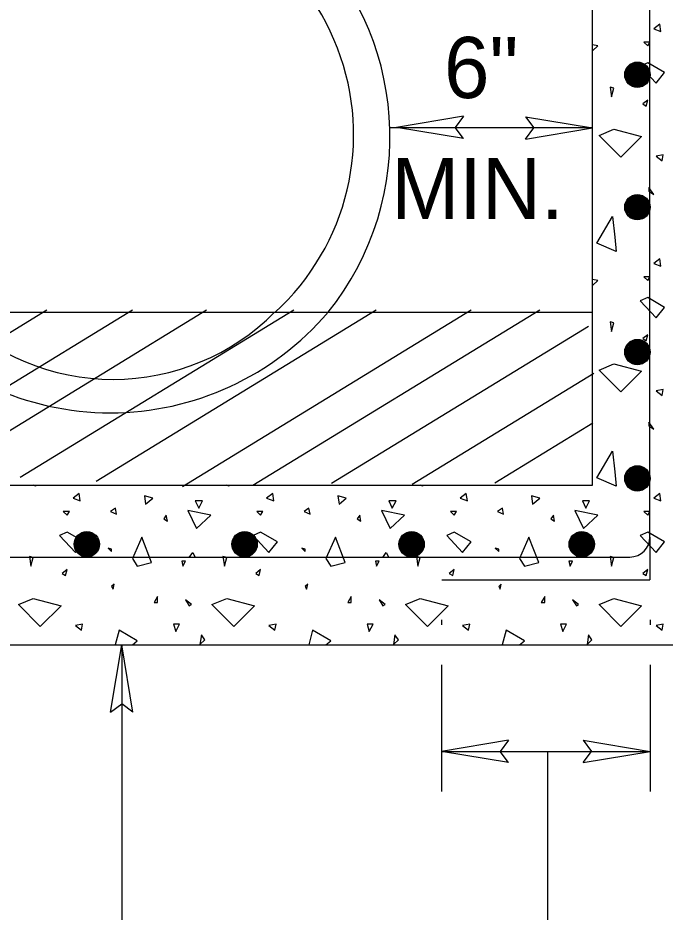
# Model space of a CAD drawing. Extents: x 5.8 to 18, y -5.2 to 5.4.
# Drawn here: x 7.37 to 8.006, y -2.394 to -1.516 of the extents above; entities that cross this region are included whole.
import ezdxf

# ---------------------------------------------------------------- set-up
doc = ezdxf.new("R2010")
doc.units = 0
for name, color, linetype in [('DETL-DIMS', 7, 'Continuous'), ('DETL-LINE', 7, 'Continuous'), ('DETL-NOTE', 7, 'Continuous'), ('DETL-PATT', 7, 'Continuous')]:
    doc.layers.add(name, color=color, linetype=linetype)

msp = doc.modelspace()

# ---------------------------------------------------------------- linework, layer by layer
at = {"layer": 'DETL-DIMS'}
for p, q in [((7.80765, -1.61271), (7.74176, -1.62369)), ((7.80765, -1.61271), (7.79941, -1.62369)), ((7.86847, -1.61322), (7.93435, -1.6242)), ((7.86847, -1.61322), (7.87671, -1.6242)), ((7.93435, -1.6242), (7.73541, -1.6242)), ((7.80765, -1.63467), (7.74176, -1.62369)), ((7.80765, -1.63467), (7.79941, -1.62369)), ((7.86847, -1.63518), (7.93435, -1.6242)), ((7.86847, -1.63518), (7.87671, -1.6242)), ((7.786, -2.10702), (7.786, -2.11216)), ((7.99098, -2.10702), (7.99098, -2.11216)), ((7.46114, -2.19765), (7.47212, -2.13177)), ((7.4831, -2.19765), (7.47212, -2.13177)), ((7.47212, -2.13177), (7.47212, -2.45765)), ((7.786, -2.15138), (7.786, -2.27557)), ((7.99098, -2.15138), (7.99098, -2.27557)), ((7.46114, -2.19765), (7.47212, -2.18942)), ((7.4831, -2.19765), (7.47212, -2.18942)), ((7.85188, -2.22538), (7.786, -2.23636)), ((7.85188, -2.22538), (7.786, -2.23636)), ((7.85188, -2.22538), (7.84365, -2.23636)), ((7.85188, -2.22538), (7.84365, -2.23636)), ((7.9251, -2.22538), (7.99098, -2.23636)), ((7.9251, -2.22538), (7.93333, -2.23636)), ((7.786, -2.23636), (7.99098, -2.23636)), ((7.85188, -2.24734), (7.786, -2.23636)), ((7.85188, -2.24734), (7.786, -2.23636)), ((7.85188, -2.24734), (7.84365, -2.23636)), ((7.85188, -2.24734), (7.84365, -2.23636)), ((7.89024, -2.23636), (7.89024, -2.87251)), ((7.9251, -2.24734), (7.99098, -2.23636)), ((7.9251, -2.24734), (7.93333, -2.23636))]:
    msp.add_line(p, q, dxfattribs=at)
at = {"layer": 'DETL-LINE'}
for p, q in [((7.93435, -1.97495), (7.93435, -0.73934)), ((7.99071, -2.02593), (7.99071, -1.28177)), ((7.00843, -1.80506), (7.93435, -1.80506)), ((7.00843, -1.97495), (7.93435, -1.97495)), ((7.99071, -2.02593), (7.99071, -2.06781)), ((6.94996, -2.04542), (7.9711, -2.04542)), ((7.78643, -2.06781), (7.99071, -2.06781)), ((6.87914, -2.13177), (8.0651, -2.13177))]:
    msp.add_line(p, q, dxfattribs=at)
for points in [[(7.98965, -1.91291), (7.98965, -1.91659), (7.99447, -1.91997)], [(7.84482, -2.07216), (7.84227, -2.07444), (7.84369, -2.07698)]]:
    msp.add_lwpolyline(points, close=True, dxfattribs=at)
for centre, radius in [((7.97844, -1.57189), 0.01247), ((7.97833, -1.57179), 0.01163), ((7.97722, -1.57179), 0.01009), ((7.97847, -1.57208), 0.01122), ((7.9788, -1.57261), 0.011), ((7.97875, -1.57222), 0.01024), ((7.97902, -1.57228), 0.00969), ((7.97763, -1.5713), 0.00834), ((7.9791, -1.57255), 0.00918), ((7.97743, -1.57228), 0.00724), ((7.97924, -1.57269), 0.00876), ((7.9791, -1.57291), 0.00835), ((7.9768, -1.57269), 0.00578), ((7.97931, -1.57291), 0.00814), ((7.97916, -1.57277), 0.00786), ((7.97951, -1.57297), 0.00751), ((7.97959, -1.57283), 0.00704), ((7.97776, -1.57242), 0.00467), ((7.97965, -1.57275), 0.00655), ((7.97965, -1.57261), 0.006), ((7.97973, -1.57277), 0.00565), ((7.97973, -1.57283), 0.0051), ((7.97994, -1.57326), 0.00488), ((7.98006, -1.57332), 0.00445), ((7.98006, -1.5732), 0.0039), ((7.98022, -1.5731), 0.00377), ((7.98022, -1.57346), 0.00347), ((7.98035, -1.57318), 0.00333), ((7.98041, -1.57326), 0.00285), ((7.98022, -1.57304), 0.00238), ((7.98049, -1.57334), 0.00212), ((7.98057, -1.57332), 0.00175), ((7.98071, -1.5734), 0.00133), ((7.98071, -1.57326), 0.00118), ((7.98112, -1.57332), 0.00148), ((7.98069, -1.57326), 0.000769), ((7.98055, -1.57326), 0.000362), ((7.98084, -1.57326), 0.00023), ((7.97844, -1.70197), 0.01247), ((7.97833, -1.70187), 0.01163), ((7.97722, -1.70187), 0.01009), ((7.97847, -1.70216), 0.01122), ((7.9788, -1.70269), 0.011), ((7.97875, -1.7023), 0.01024), ((7.97763, -1.70138), 0.00834), ((7.97902, -1.70236), 0.00969), ((7.9791, -1.70263), 0.00918), ((7.97924, -1.70277), 0.00876), ((7.97743, -1.70236), 0.00724), ((7.9791, -1.70298), 0.00835), ((7.9768, -1.70277), 0.00578), ((7.97931, -1.70298), 0.00814), ((7.97916, -1.70285), 0.00786), ((7.97951, -1.70304), 0.00751), ((7.97959, -1.70291), 0.00704), ((7.97776, -1.70249), 0.00467), ((7.97965, -1.70283), 0.00655), ((7.97965, -1.70269), 0.006), ((7.97973, -1.70285), 0.00565), ((7.97973, -1.70291), 0.0051), ((7.97994, -1.70334), 0.00488), ((7.98006, -1.7034), 0.00445), ((7.98006, -1.70328), 0.0039), ((7.98022, -1.70318), 0.00377), ((7.98022, -1.70353), 0.00347), ((7.98035, -1.70326), 0.00333), ((7.98041, -1.70334), 0.00285), ((7.98022, -1.70312), 0.00238), ((7.98049, -1.70342), 0.00212), ((7.98057, -1.7034), 0.00175), ((7.98071, -1.70348), 0.00133), ((7.98071, -1.70334), 0.00118), ((7.98112, -1.7034), 0.00148), ((7.98069, -1.70334), 0.000769), ((7.98055, -1.70334), 0.000362), ((7.98084, -1.70334), 0.00023), ((7.97844, -1.84421), 0.01247), ((7.97833, -1.8441), 0.01163), ((7.97722, -1.8441), 0.01009), ((7.97847, -1.8444), 0.01122), ((7.9788, -1.84493), 0.011), ((7.97875, -1.84453), 0.01024), ((7.97902, -1.84459), 0.00969), ((7.97763, -1.84361), 0.00834), ((7.9791, -1.84487), 0.00918), ((7.97743, -1.84459), 0.00724), ((7.97924, -1.845), 0.00876), ((7.9791, -1.84522), 0.00835), ((7.9768, -1.845), 0.00578), ((7.97931, -1.84522), 0.00814), ((7.97916, -1.84508), 0.00786), ((7.97951, -1.84528), 0.00751), ((7.97959, -1.84514), 0.00704), ((7.97776, -1.84473), 0.00467), ((7.97965, -1.84506), 0.00655), ((7.97965, -1.84493), 0.006), ((7.97973, -1.84508), 0.00565), ((7.97973, -1.84514), 0.0051), ((7.97994, -1.84557), 0.00488), ((7.98006, -1.84563), 0.00445), ((7.98006, -1.84551), 0.0039), ((7.98022, -1.84542), 0.00377), ((7.98022, -1.84577), 0.00347), ((7.98035, -1.84549), 0.00333), ((7.98041, -1.84557), 0.00285), ((7.98022, -1.84536), 0.00238), ((7.98049, -1.84565), 0.00212), ((7.98057, -1.84563), 0.00175), ((7.98071, -1.84571), 0.00133), ((7.98071, -1.84557), 0.00118), ((7.98112, -1.84563), 0.00148), ((7.98069, -1.84557), 0.000769), ((7.98055, -1.84557), 0.000362), ((7.98084, -1.84557), 0.00023), ((7.97844, -1.96825), 0.01247), ((7.97833, -1.96814), 0.01163), ((7.97847, -1.96844), 0.01122), ((7.97722, -1.96814), 0.01009), ((7.9788, -1.96897), 0.011), ((7.97875, -1.96857), 0.01024), ((7.97763, -1.96765), 0.00834), ((7.97902, -1.96863), 0.00969), ((7.9791, -1.96891), 0.00918), ((7.97743, -1.96863), 0.00724), ((7.97924, -1.96904), 0.00876), ((7.9791, -1.96926), 0.00835), ((7.9768, -1.96904), 0.00578), ((7.97931, -1.96926), 0.00814), ((7.97916, -1.96912), 0.00786), ((7.97951, -1.96932), 0.00751), ((7.97959, -1.96918), 0.00704), ((7.97776, -1.96877), 0.00467), ((7.97965, -1.9691), 0.00655), ((7.97965, -1.96897), 0.006), ((7.97973, -1.96912), 0.00565), ((7.97973, -1.96918), 0.0051), ((7.97994, -1.96961), 0.00488), ((7.98006, -1.96967), 0.00445), ((7.98006, -1.96955), 0.0039), ((7.98022, -1.96946), 0.00377), ((7.98022, -1.96981), 0.00347), ((7.98035, -1.96953), 0.00333), ((7.98041, -1.96961), 0.00285), ((7.98022, -1.9694), 0.00238), ((7.98049, -1.96969), 0.00212), ((7.98057, -1.96967), 0.00175), ((7.98071, -1.96975), 0.00133), ((7.98071, -1.96961), 0.00118), ((7.98112, -1.96967), 0.00148), ((7.98069, -1.96961), 0.000769), ((7.98055, -1.96961), 0.000362), ((7.98084, -1.96961), 0.00023), ((7.43788, -2.03295), 0.01247), ((7.43778, -2.03285), 0.01163), ((7.43666, -2.03285), 0.01009), ((7.43791, -2.03314), 0.01122), ((7.43825, -2.03367), 0.011), ((7.43819, -2.03328), 0.01024), ((7.43707, -2.03236), 0.00834), ((7.43846, -2.03334), 0.00969), ((7.43854, -2.03361), 0.00918), ((7.43687, -2.03334), 0.00724), ((7.43868, -2.03375), 0.00876), ((7.43854, -2.03396), 0.00835), ((7.43625, -2.03375), 0.00578), ((7.43876, -2.03396), 0.00814), ((7.4386, -2.03383), 0.00786), ((7.43895, -2.03402), 0.00751), ((7.43903, -2.03389), 0.00704), ((7.43909, -2.03381), 0.00655), ((7.43909, -2.03367), 0.006), ((7.59278, -2.03295), 0.01247), ((7.59268, -2.03285), 0.01163), ((7.59156, -2.03285), 0.01009), ((7.59281, -2.03314), 0.01122), ((7.59315, -2.03367), 0.011), ((7.59309, -2.03328), 0.01024), ((7.59197, -2.03236), 0.00834), ((7.59336, -2.03334), 0.00969), ((7.59344, -2.03361), 0.00918), ((7.59178, -2.03334), 0.00724), ((7.59358, -2.03375), 0.00876), ((7.59344, -2.03396), 0.00835), ((7.59115, -2.03375), 0.00578), ((7.59366, -2.03396), 0.00814), ((7.5935, -2.03383), 0.00786), ((7.59385, -2.03402), 0.00751), ((7.59393, -2.03389), 0.00704), ((7.59399, -2.03381), 0.00655), ((7.59399, -2.03367), 0.006), ((7.75675, -2.03295), 0.01247), ((7.75664, -2.03285), 0.01163), ((7.75552, -2.03285), 0.01009), ((7.75678, -2.03314), 0.01122), ((7.75711, -2.03367), 0.011), ((7.75705, -2.03328), 0.01024), ((7.75593, -2.03236), 0.00834), ((7.75732, -2.03334), 0.00969), ((7.7574, -2.03361), 0.00918), ((7.75574, -2.03334), 0.00724), ((7.75754, -2.03375), 0.00876), ((7.7574, -2.03396), 0.00835), ((7.75511, -2.03375), 0.00578), ((7.75762, -2.03396), 0.00814), ((7.75746, -2.03383), 0.00786), ((7.75781, -2.03402), 0.00751), ((7.75789, -2.03389), 0.00704), ((7.75795, -2.03381), 0.00655), ((7.75795, -2.03367), 0.006), ((7.9238, -2.03295), 0.01247), ((7.9237, -2.03285), 0.01163), ((7.92258, -2.03285), 0.01009), ((7.92383, -2.03314), 0.01122), ((7.92417, -2.03367), 0.011), ((7.92411, -2.03328), 0.01024), ((7.92299, -2.03236), 0.00834), ((7.92438, -2.03334), 0.00969), ((7.92446, -2.03361), 0.00918), ((7.9228, -2.03334), 0.00724), ((7.9246, -2.03375), 0.00876), ((7.92446, -2.03396), 0.00835), ((7.92217, -2.03375), 0.00578), ((7.92468, -2.03396), 0.00814), ((7.92452, -2.03383), 0.00786), ((7.92487, -2.03402), 0.00751), ((7.92495, -2.03389), 0.00704), ((7.92501, -2.03381), 0.00655), ((7.92501, -2.03367), 0.006), ((7.43721, -2.03347), 0.00467), ((7.43917, -2.03383), 0.00565), ((7.43917, -2.03389), 0.0051), ((7.43938, -2.03432), 0.00488), ((7.4395, -2.03438), 0.00445), ((7.4395, -2.03426), 0.0039), ((7.43966, -2.03416), 0.00377), ((7.43966, -2.03451), 0.00347), ((7.4398, -2.03424), 0.00333), ((7.43985, -2.03432), 0.00285), ((7.43966, -2.0341), 0.00238), ((7.43993, -2.03439), 0.00212), ((7.44001, -2.03438), 0.00175), ((7.44015, -2.03445), 0.00133), ((7.44015, -2.03432), 0.00118), ((7.44056, -2.03438), 0.00148), ((7.44013, -2.03432), 0.000769), ((7.43999, -2.03432), 0.000362), ((7.44029, -2.03432), 0.00023), ((7.59211, -2.03347), 0.00467), ((7.59407, -2.03383), 0.00565), ((7.59407, -2.03389), 0.0051), ((7.59429, -2.03432), 0.00488), ((7.5944, -2.03438), 0.00445), ((7.5944, -2.03426), 0.0039), ((7.59456, -2.03416), 0.00377), ((7.59456, -2.03451), 0.00347), ((7.5947, -2.03424), 0.00333), ((7.59476, -2.03432), 0.00285), ((7.59456, -2.0341), 0.00238), ((7.59483, -2.03439), 0.00212), ((7.59491, -2.03438), 0.00175), ((7.59505, -2.03445), 0.00133), ((7.59505, -2.03432), 0.00118), ((7.59546, -2.03438), 0.00148), ((7.59503, -2.03432), 0.000769), ((7.59489, -2.03432), 0.000362), ((7.59519, -2.03432), 0.00023), ((7.75607, -2.03347), 0.00467), ((7.75803, -2.03383), 0.00565), ((7.75803, -2.03389), 0.0051), ((7.75825, -2.03432), 0.00488), ((7.75836, -2.03438), 0.00445), ((7.75836, -2.03426), 0.0039), ((7.75852, -2.03416), 0.00377), ((7.75852, -2.03451), 0.00347), ((7.75866, -2.03424), 0.00333), ((7.75872, -2.03432), 0.00285), ((7.75852, -2.0341), 0.00238), ((7.7588, -2.03439), 0.00212), ((7.75887, -2.03438), 0.00175), ((7.75901, -2.03445), 0.00133), ((7.75901, -2.03432), 0.00118), ((7.75942, -2.03438), 0.00148), ((7.75899, -2.03432), 0.000769), ((7.75885, -2.03432), 0.000362), ((7.75915, -2.03432), 0.00023), ((7.92313, -2.03347), 0.00467), ((7.92509, -2.03383), 0.00565), ((7.92509, -2.03389), 0.0051), ((7.92531, -2.03432), 0.00488), ((7.92542, -2.03438), 0.00445), ((7.92542, -2.03426), 0.0039), ((7.92558, -2.03416), 0.00377), ((7.92558, -2.03451), 0.00347), ((7.92572, -2.03424), 0.00333), ((7.92578, -2.03432), 0.00285), ((7.92558, -2.0341), 0.00238), ((7.92585, -2.03439), 0.00212), ((7.92593, -2.03438), 0.00175), ((7.92607, -2.03445), 0.00133), ((7.92607, -2.03432), 0.00118), ((7.92648, -2.03438), 0.00148), ((7.92605, -2.03432), 0.000769), ((7.92591, -2.03432), 0.000362), ((7.92621, -2.03432), 0.00023)]:
    msp.add_circle(centre, radius, dxfattribs=at)
for centre, radius, start, end in [((7.461, -1.63265), 0.27454, 321.09641, 218.89267), ((7.46386, -1.6306), 0.23592, 312.23829, 227.67559), ((7.46096, -1.62322), 0.28059, 220.39706, 319.60294), ((7.46362, -1.64743), 0.22364, 224.81552, 315.18448), ((7.9711, -2.02581), 0.01961, 270, 360)]:
    msp.add_arc(centre, radius, start, end, dxfattribs=at)
at = {"layer": 'DETL-PATT'}
for p, q in [((7.12051, -1.97287), (7.39867, -1.80287)), ((7.20835, -1.97051), (7.48267, -1.80287)), ((7.28114, -1.97044), (7.55529, -1.80287)), ((7.37227, -1.96718), (7.64114, -1.80287)), ((7.44694, -1.97087), (7.7218, -1.80287)), ((7.53188, -1.97604), (7.81522, -1.80287)), ((7.60094, -1.97502), (7.88263, -1.80287)), ((7.67796, -1.97306), (7.93047, -1.81875)), ((7.75733, -1.974), (7.93569, -1.86498)), ((7.83859, -1.97255), (7.93471, -1.91381))]:
    msp.add_line(p, q, dxfattribs=at)
for points in [[(8.00039, -1.52216), (7.99447, -1.52695), (8.00153, -1.52949)], [(7.98486, -1.53993), (7.98851, -1.54361), (7.99078, -1.53993)], [(7.98118, -1.56365), (7.99671, -1.58032), (8.00518, -1.56985), (7.98851, -1.56028)], [(7.95153, -1.58397), (7.95294, -1.59357), (7.95522, -1.5851)], [(7.98373, -1.60063), (7.9871, -1.60291), (7.98851, -1.59698)], [(7.95522, -1.62549), (7.98259, -1.63255), (7.96227, -1.65287), (7.94082, -1.63142)], [(7.99671, -1.65173), (8.00263, -1.65655), (8.00376, -1.65063)], [(7.98965, -1.68251), (7.98965, -1.6862), (7.99447, -1.68957)], [(7.95635, -1.73138), (7.95745, -1.74549), (7.93855, -1.7373), (7.95408, -1.71102)], [(8.00039, -1.75255), (7.99447, -1.75734), (8.00153, -1.75989)], [(7.98486, -1.77032), (7.98851, -1.774), (7.99078, -1.77032)], [(7.98118, -1.79404), (7.99671, -1.81071), (8.00518, -1.80028), (7.98851, -1.79067)], [(7.95153, -1.8144), (7.95294, -1.82397), (7.95522, -1.81549)], [(7.98373, -1.83102), (7.9871, -1.8333), (7.98851, -1.82738)], [(7.95522, -1.85589), (7.98259, -1.86295), (7.96227, -1.88326), (7.94082, -1.86181)], [(7.99671, -1.88216), (8.00263, -1.88695), (8.00376, -1.88102)], [(7.95635, -1.96177), (7.95745, -1.97589), (7.93855, -1.96769), (7.95408, -1.94146)], [(7.43031, -1.98295), (7.42439, -1.98773), (7.43145, -1.99028)], [(7.62035, -1.98295), (7.61439, -1.98773), (7.62145, -1.99028)], [(7.81035, -1.98295), (7.80443, -1.98773), (7.81149, -1.99028)], [(8.00039, -1.98295), (7.99447, -1.98773), (8.00153, -1.99028)], [(7.49439, -1.98549), (7.49553, -1.99369), (7.50259, -1.98773)], [(7.54439, -1.99028), (7.54776, -1.99734), (7.55145, -1.99028)], [(7.68443, -1.98549), (7.68557, -1.99369), (7.69263, -1.98773)], [(7.73439, -1.99028), (7.7378, -1.99734), (7.74145, -1.99028)], [(7.87447, -1.98549), (7.87557, -1.99369), (7.88263, -1.98773)], [(7.92443, -1.99028), (7.9278, -1.99734), (7.93149, -1.99028)], [(7.41478, -2.00075), (7.41847, -2.0044), (7.42071, -2.00075)], [(7.4611, -2.00075), (7.46702, -2.00326), (7.46588, -1.99734)], [(7.53706, -1.99961), (7.54553, -2.01738), (7.55965, -2.0044)], [(7.60482, -2.00075), (7.60847, -2.0044), (7.61075, -2.00075)], [(7.6511, -2.00075), (7.65706, -2.00326), (7.65592, -1.99734)], [(7.72706, -1.99961), (7.73553, -2.01738), (7.74965, -2.0044)], [(7.79482, -2.00075), (7.79851, -2.0044), (7.80075, -2.00075)], [(7.84114, -2.00075), (7.84706, -2.00326), (7.84592, -1.99734)], [(7.9171, -1.99961), (7.92557, -2.01738), (7.93969, -2.0044)], [(7.98486, -2.00075), (7.98851, -2.0044), (7.99078, -2.00075)], [(7.51333, -2.00808), (7.51698, -2.01032), (7.51588, -2.0044)], [(7.70333, -2.00808), (7.70702, -2.01032), (7.70588, -2.0044)], [(7.89337, -2.00808), (7.89706, -2.01032), (7.89592, -2.0044)], [(7.4111, -2.02444), (7.42663, -2.0411), (7.4351, -2.03067), (7.41847, -2.02106)], [(7.48733, -2.0544), (7.50145, -2.05071), (7.49188, -2.02585), (7.48255, -2.04702)], [(7.60114, -2.02444), (7.61667, -2.0411), (7.62514, -2.03067), (7.60847, -2.02106)], [(7.67737, -2.0544), (7.69149, -2.05071), (7.68188, -2.02585), (7.67259, -2.04702)], [(7.79118, -2.02444), (7.80671, -2.0411), (7.81518, -2.03067), (7.79851, -2.02106)], [(7.86741, -2.0544), (7.88153, -2.05071), (7.87192, -2.02585), (7.86259, -2.04702)], [(7.98118, -2.02444), (7.99671, -2.0411), (8.00518, -2.03067), (7.98851, -2.02106)], [(7.46224, -2.03773), (7.45882, -2.03659), (7.46224, -2.03997)], [(7.65224, -2.03773), (7.64886, -2.03659), (7.65224, -2.03997)], [(7.84227, -2.03773), (7.83886, -2.03659), (7.84227, -2.03997)], [(7.38145, -2.04479), (7.38286, -2.0544), (7.38514, -2.04593)], [(7.54184, -2.0411), (7.54439, -2.04593), (7.53847, -2.04593)], [(7.57149, -2.04479), (7.5729, -2.0544), (7.57518, -2.04593)], [(7.73188, -2.0411), (7.73439, -2.04593), (7.72847, -2.04593)], [(7.76153, -2.04479), (7.76294, -2.0544), (7.76518, -2.04593)], [(7.92188, -2.0411), (7.92443, -2.04593), (7.91851, -2.04593)], [(7.95153, -2.04479), (7.95294, -2.0544), (7.95522, -2.04593)], [(7.5311, -2.04957), (7.53224, -2.0544), (7.53478, -2.04957)], [(7.72114, -2.04957), (7.72227, -2.0544), (7.72482, -2.04957)], [(7.91118, -2.04957), (7.91227, -2.0544), (7.91482, -2.04957)], [(7.41365, -2.06146), (7.41706, -2.06369), (7.41847, -2.05777)], [(7.60369, -2.06146), (7.60706, -2.06369), (7.60847, -2.05777)], [(7.79369, -2.06146), (7.7971, -2.06369), (7.79851, -2.05777)], [(7.98373, -2.06146), (7.9871, -2.06369), (7.98851, -2.05777)], [(7.46475, -2.07216), (7.46224, -2.07444), (7.46365, -2.07698)], [(7.65478, -2.07216), (7.65224, -2.07444), (7.65365, -2.07698)], [(7.38514, -2.08628), (7.41251, -2.09334), (7.3922, -2.11369), (7.37075, -2.0922)], [(7.50741, -2.08404), (7.504, -2.08997), (7.50741, -2.08997)], [(7.53847, -2.09334), (7.54071, -2.0922), (7.53478, -2.08742)], [(7.57518, -2.08628), (7.60255, -2.09334), (7.58224, -2.11369), (7.56075, -2.0922)], [(7.69741, -2.08404), (7.69404, -2.08997), (7.69741, -2.08997)], [(7.72847, -2.09334), (7.73075, -2.0922), (7.72482, -2.08742)], [(7.76518, -2.08628), (7.79259, -2.09334), (7.77224, -2.11369), (7.75078, -2.0922)], [(7.88745, -2.08404), (7.88404, -2.08997), (7.88745, -2.08997)], [(7.91851, -2.09334), (7.92075, -2.0922), (7.91482, -2.08742)], [(7.95522, -2.08628), (7.98259, -2.09334), (7.96227, -2.11369), (7.94082, -2.0922)], [(7.42663, -2.11255), (7.43259, -2.11734), (7.43369, -2.11142)], [(7.52294, -2.11142), (7.52518, -2.11848), (7.52886, -2.11142)], [(7.61667, -2.11255), (7.62259, -2.11734), (7.62373, -2.11142)], [(7.71294, -2.11142), (7.71522, -2.11848), (7.71886, -2.11142)], [(7.80671, -2.11255), (7.81263, -2.11734), (7.81376, -2.11142)], [(7.90298, -2.11142), (7.90522, -2.11848), (7.9089, -2.11142)], [(7.99671, -2.11255), (8.00263, -2.11734), (8.00376, -2.11142)], [(7.55031, -2.12185), (7.5489, -2.13146), (7.55369, -2.12667)], [(7.74035, -2.12185), (7.73894, -2.13146), (7.74373, -2.12667)], [(7.93035, -2.12185), (7.92894, -2.13146), (7.93376, -2.12667)]]:
    msp.add_lwpolyline(points, close=True, dxfattribs=at)
for points in [[(7.93435, -1.54851), (7.93969, -1.54361), (7.93435, -1.54248)], [(7.93435, -1.77891), (7.93969, -1.774), (7.93435, -1.77287)], [(7.38733, -1.97495), (7.38741, -1.97589), (7.38525, -1.97495)], [(7.57733, -1.97495), (7.57741, -1.97589), (7.57525, -1.97495)], [(7.76737, -1.97495), (7.76745, -1.97589), (7.76529, -1.97495)], [(7.48263, -2.13177), (7.48733, -2.12781), (7.46957, -2.11734), (7.46576, -2.13177)], [(7.67267, -2.13177), (7.67737, -2.12781), (7.65957, -2.11734), (7.6558, -2.13177)], [(7.86267, -2.13177), (7.86741, -2.12781), (7.84961, -2.11734), (7.8458, -2.13177)]]:
    msp.add_lwpolyline(points, dxfattribs=at)

# ---------------------------------------------------------------- texts
at = {"layer": 'DETL-NOTE'}
for s, p in [('6"', (7.78855, -1.59479)), ('MIN.', (7.73663, -1.71361))]:
    msp.add_text(s, height=0.06, dxfattribs=at).set_placement(p)

doc.saveas('drawing.dxf')
